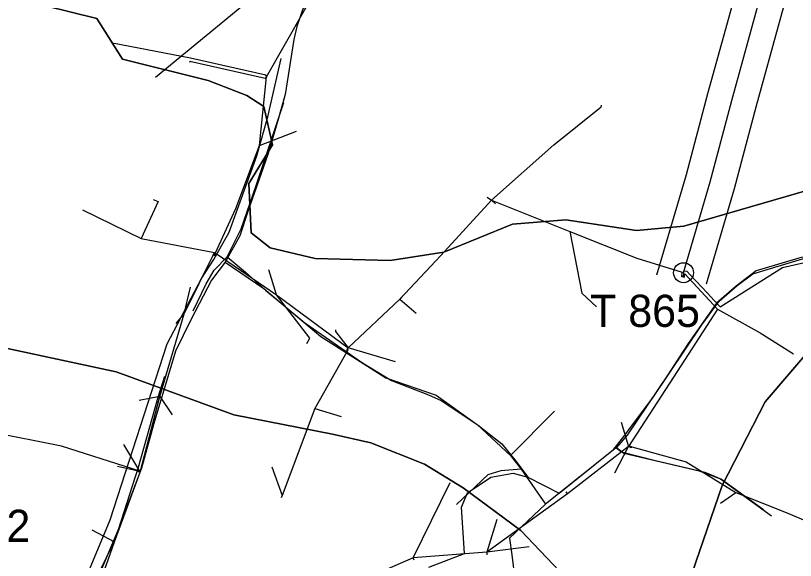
# Model space of a CAD drawing. Extents: x -694504 to -690518, y -983661 to -978958.
# Drawn here: x -692421.3 to -692057.3, y -981693.8 to -981439.4 of the extents above; entities that cross this region are included whole.
import ezdxf

# ---------------------------------------------------------------- set-up
doc = ezdxf.new("R2010")
doc.units = 0
for name, color, linetype in [('BPEJ', 7, 'Continuous'), ('kabelové a venkovní rozvody telefonu', 7, 'Continuous'), ('kanalizace', 7, 'Continuous'), ('ochranné pásmo vedení', 7, 'Continuous'), ('trafostanice', 7, 'Continuous'), ('třídy přednosti v ochraně ZP', 7, 'Continuous'), ('vedení NN', 7, 'Continuous'), ('vedení VN 35kV', 7, 'Continuous'), ('vodovodní řad', 7, 'Continuous')]:
    doc.layers.add(name, color=color, linetype=linetype)

msp = doc.modelspace()

# ---------------------------------------------------------------- linework, layer by layer
at = {"layer": 'BPEJ'}
for points in [[(-692030.4, -981514.81), (-692109.4, -981537.81), (-692131.4, -981539.81), (-692164.4, -981534.81), (-692189.4, -981536.81), (-692221.4, -981549.81), (-692246.4, -981553.81), (-692281.4, -981552.81), (-692302.4, -981547.81), (-692311.4, -981540.81), (-692312.4, -981517.81), (-692301.4, -981499.81), (-692305.4, -981481.81), (-692313.4, -981476.81), (-692331.4, -981469.81), (-692371.4, -981459.81), (-692383.4, -981440.81), (-692419.4, -981431.81)], [(-692419.4, -981431.81), (-692383.4, -981440.81), (-692371.4, -981459.81), (-692331.4, -981469.81), (-692313.4, -981476.81), (-692305.4, -981481.81), (-692301.4, -981499.81), (-692312.4, -981517.81), (-692311.4, -981540.81), (-692302.4, -981547.81), (-692281.4, -981552.81), (-692246.4, -981553.81), (-692221.4, -981549.81), (-692189.4, -981536.81), (-692164.4, -981534.81), (-692131.4, -981539.81), (-692109.4, -981537.81), (-692030.4, -981514.81)], [(-692048.4, -981592.81), (-692071.4, -981619.81), (-692091.4, -981658.81), (-692121.4, -981745.81), (-692122.4, -981762.81), (-692129.4, -981747.81), (-692146.4, -981720.81), (-692185.4, -981679.81), (-692212.4, -981659.81), (-692230.4, -981648.81), (-692255.4, -981638.81), (-692273.4, -981634.81), (-692319.4, -981625.81), (-692374.4, -981605.81), (-692448.4, -981589.81)], [(-692448.4, -981589.81), (-692374.4, -981605.81), (-692319.4, -981625.81), (-692273.4, -981634.81), (-692255.4, -981638.81), (-692230.4, -981648.81), (-692212.4, -981659.81), (-692185.4, -981679.81), (-692146.4, -981720.81), (-692129.4, -981747.81), (-692122.4, -981762.81), (-692122.4, -981762.81), (-692131.4, -981839.81), (-692140.4, -981853.81), (-692186.4, -981898.81), (-692262.4, -982000.81), (-692301.4, -982096.81)], [(-692040.4, -981946.81), (-692057.4, -981978.81), (-692066.4, -982000.81), (-692073.4, -982026.81), (-692083.4, -981992.81), (-692073.4, -981913.81), (-692069.4, -981844.81), (-692080.4, -981831.81), (-692109.4, -981808.81), (-692131.4, -981839.81), (-692122.4, -981762.81), (-692121.4, -981745.81), (-692091.4, -981658.81), (-692071.4, -981619.81), (-692048.4, -981592.81)]]:
    msp.add_lwpolyline(points, dxfattribs=at)
at = {"layer": 'kabelové a venkovní rozvody telefonu'}
for points in [[(-692322.48, -981552.13), (-692316.04, -981538.95), (-692309.01, -981518.73), (-692296.14, -981479.93)], [(-692338.37, -981577.29), (-692332.4, -981564.62), (-692328.62, -981558.33), (-692322.48, -981552.13), (-692313.98, -981559.16), (-692304.61, -981567.66), (-692286.25, -981582.81), (-692259.31, -981601.57), (-692245.84, -981609.77), (-692228.57, -981616.51), (-692222.71, -981619.14), (-692205.43, -981630.57), (-692194.31, -981639.36), (-692187.57, -981647.56), (-692182.22, -981654.98)], [(-692141.29, -981640.86), (-692138.01, -981636.65), (-692123.86, -981617.8), (-692101.02, -981583.81), (-692092.86, -981572.73), (-692084.43, -981565.46), (-692077.19, -981559.95), (-692048.89, -981551.49)], [(-692351.73, -981607.84), (-692354.94, -981617.65), (-692364.02, -981650.47), (-692374.85, -981683.8), (-692381, -981696.69), (-692385.95, -981706.26), (-692390.35, -981717.4), (-692391.52, -981722.38), (-692391.52, -981725.6), (-692389.76, -981730.29), (-692384.78, -981735.27), (-692373.07, -981744.64), (-692354.95, -981754.1)], [(-692228.42, -981696.87), (-692211.68, -981690.59), (-692213.16, -981668.95), (-692210.33, -981662.17), (-692199.42, -981654.98), (-692189.09, -981652.97), (-692182.22, -981654.98), (-692167.63, -981662.43), (-692142.15, -981641.97), (-692141.29, -981640.86), (-692138.46, -981643.07), (-692122.65, -981647.17), (-692102.74, -981651.85), (-692092.19, -981655.66), (-692082.53, -981662.7), (-692068.47, -981672.95)]]:
    msp.add_lwpolyline(points, dxfattribs=at)
at = {"layer": 'kanalizace'}
msp.add_lwpolyline([(-692637.3, -982018.94), (-692543.86, -981996.43), (-692482.24, -981915), (-692389.85, -981795.54), (-692370.2, -981769.76), (-692361.24, -981760.23), (-692369.79, -981750.51), (-692394.74, -981731.55), (-692395.7, -981719.37), (-692377.18, -981674.9), (-692350.54, -981592.69), (-692334.59, -981562.19), (-692328.73, -981553.37), (-692321.59, -981540.53), (-692308.62, -981504.97), (-692303.5, -981486.69), (-692297.29, -981459.54)], dxfattribs=at)
at = {"layer": 'ochranné pásmo vedení'}
for points in [[(-692476.97, -981718.1), (-692516.45, -981680.3), (-692507.47, -981641.12), (-692491.56, -981571.66), (-692478.56, -981516.66), (-692467.55, -981468.63), (-692453.55, -981407.64), (-692440.55, -981351.64), (-692429.53, -981303.54), (-692425.91, -981286.65), (-692239.14, -981321.55), (-692136.15, -981340.55), (-692063.84, -981354.16), (-692072.29, -981383.76), (-692085.31, -981428.8), (-692098.34, -981475.94), (-692108.32, -981513.84), (-692122.09, -981560.59)], [(-692098.78, -981564.62), (-692085.68, -981520.16), (-692075.66, -981482.06), (-692062.69, -981435.2), (-692049.71, -981390.24), (-692040.57, -981358.27), (-691970.98, -981369.58), (-691892.99, -981383.58), (-691578.35, -981435.35), (-691505.97, -981436.12), (-691403.79, -981436.1), (-691320.85, -981435.75), (-691226.93, -981433.75), (-691115.11, -981434.75), (-691018, -981435.75), (-690919.94, -981434.75), (-690865, -981434.75), (-690798.01, -981434.75), (-690720.4, -981434.84), (-690660.99, -981434.75), (-690632.73, -981444.66)]]:
    msp.add_lwpolyline(points, dxfattribs=at)
at = {"layer": 'trafostanice'}
msp.add_ellipse((-692109.51, -981559.46), major_axis=(0, 4.66), ratio=0.997816, dxfattribs=at)
at = {"layer": 'vedení NN'}
for points in [[(-692304.18, -981468.07), (-692286.37, -981436.95), (-692269.09, -981406.97), (-692250.04, -981388), (-692230.09, -981367.77)], [(-692304.18, -981468.07), (-692286.37, -981436.95), (-692269.09, -981406.97), (-692250.04, -981388), (-692230.09, -981367.77)], [(-692304.18, -981468.07), (-692304.47, -981467.19), (-692339.62, -981459.26), (-692376.04, -981452.38)], [(-692304.18, -981468.07), (-692304.47, -981467.19), (-692339.62, -981459.26), (-692376.04, -981452.38)], [(-692304.18, -981468.07), (-692304.79, -981468.75), (-692339.98, -981460.82), (-692340.11, -981461.26)], [(-692304.18, -981468.07), (-692304.79, -981468.75), (-692339.98, -981460.82), (-692340.11, -981461.26)], [(-692307.49, -981500.06), (-692304.18, -981468.07)], [(-692307.49, -981500.06), (-692304.18, -981468.07)], [(-692199.19, -981525.67), (-692169.98, -981499.82), (-692148.01, -981482.08), (-692147.87, -981481.2)], [(-692307.49, -981500.06), (-692290.15, -981493.46)], [(-692307.49, -981500.06), (-692290.15, -981493.46)], [(-692328.06, -981550.23), (-692318.5, -981529.53), (-692307.49, -981500.06)], [(-692328.06, -981550.23), (-692318.5, -981529.53), (-692307.49, -981500.06)], [(-692201.2, -981524.18), (-692199.19, -981525.67)], [(-692357.03, -981525.35), (-692354.72, -981526.22), (-692362.73, -981543.46)], [(-692357.03, -981525.35), (-692354.72, -981526.22), (-692362.73, -981543.46)], [(-692241.88, -981571.78), (-692222.74, -981551.41), (-692199.19, -981525.67)], [(-692241.88, -981571.78), (-692222.74, -981551.41), (-692199.19, -981525.67)], [(-692199.19, -981525.67), (-692162.59, -981540.3)], [(-692199.19, -981525.67), (-692197.34, -981527.36)], [(-692390.11, -981530.07), (-692362.73, -981543.46)], [(-692390.11, -981530.07), (-692362.73, -981543.46)], [(-692162.59, -981540.3), (-692157.02, -981569.01), (-692150.09, -981575.45)], [(-692162.59, -981540.3), (-692131.29, -981552.63), (-692110.09, -981559.22)], [(-692362.73, -981543.46), (-692328.4, -981550.02)], [(-692362.73, -981543.46), (-692328.4, -981550.02)], [(-692092.46, -981575.4), (-692063.34, -981556.99), (-692020.86, -981547.32)], [(-692342.67, -981578.61), (-692328.4, -981550.02)], [(-692342.67, -981578.61), (-692328.4, -981550.02)], [(-692328.67, -981551.26), (-692329.03, -981551.09), (-692328.4, -981550.02)], [(-692328.67, -981551.26), (-692329.03, -981551.09), (-692328.4, -981550.02)], [(-692328.67, -981551.26), (-692328.06, -981550.23)], [(-692328.67, -981551.26), (-692328.06, -981550.23)], [(-692328.67, -981551.26), (-692328.3, -981551.43), (-692327.71, -981550.43)], [(-692328.67, -981551.26), (-692328.3, -981551.43), (-692327.71, -981550.43)], [(-692327.71, -981550.43), (-692299.46, -981569.76)], [(-692327.71, -981550.43), (-692299.46, -981569.76)], [(-692299.46, -981569.76), (-692303.13, -981558.09)], [(-692299.46, -981569.76), (-692303.13, -981558.09)], [(-692109.65, -981561.46), (-692110.25, -981561.41), (-692110.09, -981559.22)], [(-692109.65, -981561.46), (-692109.45, -981561.46), (-692109.31, -981559.55), (-692109.24, -981558.6), (-692107.98, -981558.71), (-692106.21, -981560.63), (-692098.37, -981569.04), (-692095.22, -981572.43), (-692092.46, -981575.4)], [(-692109.65, -981561.46), (-692109.05, -981561.5), (-692108.95, -981560.04), (-692093.7, -981576.44)], [(-692342.67, -981578.61), (-692339.67, -981566.27)], [(-692342.67, -981578.61), (-692339.67, -981566.27)], [(-692299.46, -981569.76), (-692265.99, -981594.6)], [(-692285.28, -981592.44), (-692283.96, -981589.97), (-692299.46, -981569.76)], [(-692299.46, -981569.76), (-692265.99, -981594.6)], [(-692285.28, -981592.44), (-692283.96, -981589.97), (-692299.46, -981569.76)], [(-692265.99, -981594.6), (-692241.88, -981571.78)], [(-692265.99, -981594.6), (-692241.88, -981571.78)], [(-692241.08, -981570.79), (-692241.88, -981571.78)], [(-692241.08, -981570.79), (-692241.88, -981571.78)], [(-692241.88, -981571.78), (-692234.39, -981578.41)], [(-692241.88, -981571.78), (-692234.39, -981578.41)], [(-692354.05, -981617.2), (-692342.67, -981578.61)], [(-692354.05, -981617.2), (-692342.67, -981578.61)], [(-692346.29, -981583.25), (-692342.67, -981578.61)], [(-692346.29, -981583.25), (-692342.67, -981578.61)], [(-692093.7, -981576.44), (-692114.24, -981608.18), (-692135.16, -981640.63)], [(-692093.7, -981576.44), (-692073.72, -981587.56), (-692058.16, -981597.26)], [(-692271.99, -981586.18), (-692271.99, -981586.97), (-692265.99, -981594.6)], [(-692271.99, -981586.18), (-692271.99, -981586.97), (-692265.99, -981594.6)], [(-692363.24, -981652.11), (-692399.84, -981640.37), (-692432.85, -981633.91), (-692467.53, -981622.8), (-692500.59, -981611.45), (-692535.39, -981599.72), (-692572.99, -981587.27)], [(-692363.24, -981652.11), (-692399.84, -981640.37), (-692432.85, -981633.91), (-692467.53, -981622.8), (-692500.59, -981611.45), (-692535.39, -981599.72), (-692572.99, -981587.27)], [(-692266.59, -981595.73), (-692266.42, -981595.84), (-692265.99, -981595.26), (-692281.69, -981622.84)], [(-692266.59, -981595.73), (-692266.42, -981595.84), (-692265.99, -981595.26), (-692281.69, -981622.84)], [(-692266.59, -981595.73), (-692266.75, -981595.61), (-692265.99, -981594.6)], [(-692266.59, -981595.73), (-692266.75, -981595.61), (-692265.99, -981594.6)], [(-692244, -981601), (-692265.99, -981594.6)], [(-692244, -981601), (-692265.99, -981594.6)], [(-692354.05, -981617.2), (-692363.55, -981619.11)], [(-692354.05, -981617.2), (-692363.55, -981619.11)], [(-692363.14, -981652.52), (-692354.05, -981617.2)], [(-692363.14, -981652.52), (-692354.05, -981617.2)], [(-692354.05, -981617.2), (-692348.28, -981625.76)], [(-692354.05, -981617.2), (-692348.28, -981625.76)], [(-692281.69, -981622.84), (-692296.9, -981663.39)], [(-692281.69, -981622.84), (-692296.9, -981663.39)], [(-692281.69, -981622.84), (-692269.37, -981626.66)], [(-692281.69, -981622.84), (-692269.37, -981626.66)], [(-692138.57, -981629.29), (-692135.16, -981640.63)], [(-692363.24, -981652.11), (-692370.79, -981639.61)], [(-692363.24, -981652.11), (-692370.79, -981639.61)], [(-692135.16, -981640.63), (-692163.66, -981662.66)], [(-692141.57, -981652.95), (-692135.16, -981640.63)], [(-692133.93, -981641), (-692134.01, -981641.19), (-692135.16, -981640.63)], [(-692134.69, -981640.41), (-692108.2, -981647.79), (-692085.04, -981662.04)], [(-692133.93, -981641), (-692133.85, -981640.82), (-692134.69, -981640.41)], [(-692373.77, -981649.74), (-692363.24, -981652.11)], [(-692373.77, -981649.74), (-692363.24, -981652.11)], [(-692301.65, -981650.02), (-692296.9, -981663.39)], [(-692301.65, -981650.02), (-692296.9, -981663.39)], [(-692375.21, -981685.03), (-692363.14, -981652.52)], [(-692375.21, -981685.03), (-692363.14, -981652.52)], [(-692363.14, -981652.52), (-692364.16, -981652.38), (-692364.14, -981652.18)], [(-692363.14, -981652.52), (-692364.16, -981652.38), (-692364.14, -981652.18)], [(-692364.14, -981652.18), (-692364.13, -981651.99), (-692363.24, -981652.11)], [(-692364.14, -981652.18), (-692364.13, -981651.99), (-692363.24, -981652.11)], [(-692235.68, -981692.51), (-692218.43, -981657.42)], [(-692235.68, -981692.51), (-692218.43, -981657.42)], [(-692163.66, -981662.66), (-692201.35, -981689.88)], [(-692164.46, -981661.68), (-692163.66, -981662.66)], [(-692092.18, -981667.12), (-692085.04, -981662.04)], [(-692085.04, -981662.04), (-692060.84, -981671.79)], [(-692296.9, -981663.39), (-692297.3, -981664.6)], [(-692296.9, -981663.39), (-692297.3, -981664.6)], [(-692060.84, -981671.79), (-692032.41, -981683.91), (-692001.06, -981694.15), (-691966.1, -981706.21), (-691937.97, -981715.65), (-691916.06, -981721.56), (-691918.14, -981720.74)], [(-692196.67, -981674.69), (-692201.35, -981689.88)], [(-692385.68, -981679.52), (-692375.21, -981685.03)], [(-692385.68, -981679.52), (-692375.21, -981685.03)], [(-692376.41, -981684.64), (-692375.21, -981685.03)], [(-692376.41, -981684.64), (-692375.21, -981685.03)], [(-692389.74, -981726.41), (-692375.21, -981685.03)], [(-692389.74, -981726.41), (-692375.21, -981685.03)], [(-692181.51, -981687.44), (-692201.35, -981689.88)], [(-692201.35, -981689.88), (-692235.68, -981692.51)], [(-692201.35, -981689.88), (-692235.68, -981692.51)], [(-692201.35, -981689.88), (-692201.3, -981691.14)], [(-692235.68, -981692.51), (-692266.02, -981705.85)], [(-692235.68, -981692.51), (-692266.02, -981705.85)], [(-692235.3, -981693.72), (-692235.68, -981692.51)], [(-692235.3, -981693.72), (-692235.68, -981692.51)]]:
    msp.add_lwpolyline(points, dxfattribs=at)
at = {"layer": 'vedení VN 35kV'}
msp.add_lwpolyline([(-692109.51, -981559.46), (-692097, -981517), (-692087, -981479), (-692074, -981432), (-692061, -981387), (-692049, -981345), (-692029, -981294), (-692008, -981241), (-691986, -981188), (-691990, -981131), (-691993, -981064), (-691997, -980994), (-691952, -980955), (-691906, -980915), (-691864.8, -980876.87), (-691830.33, -980911.56), (-691803.29, -980937.37)], dxfattribs=at)
at = {"layer": 'vodovodní řad'}
for points in [[(-691952.28, -981239.87), (-691994.16, -981283.53), (-692016.03, -981284.05), (-692075.58, -981304.29), (-692142.96, -981360.36), (-692143.71, -981380.97), (-692213.37, -981379.85), (-692228.6, -981388.76), (-692264.18, -981392.95), (-692318.32, -981437.42), (-692356, -981468.38)], [(-692284.73, -981428.92), (-692289.95, -981444.58), (-692291.44, -981450.54), (-692295.54, -981476.22), (-692298.9, -981488.34), (-692303.54, -981504.27), (-692312.83, -981530.88), (-692316.57, -981542.29), (-692323.49, -981554.53), (-692329.81, -981562.87), (-692339.45, -981581.45), (-692346.6, -981596.1), (-692356.78, -981629.87), (-692362.51, -981650.64), (-692373.6, -981679.74), (-692384.92, -981706.74), (-692389.75, -981718.96), (-692388.26, -981731.64), (-692361.43, -981749.91), (-692367.98, -981754.94), (-692376.35, -981765.9), (-692385.69, -981778.47), (-692399.12, -981797.49), (-692433.91, -981841.96)], [(-691925.74, -981524.9), (-691945.82, -981526.14), (-691955.93, -981527.64), (-692017.33, -981543.71), (-692055.72, -981552.66), (-692075.66, -981558.63), (-692084.97, -981565.71), (-692094.1, -981573.73), (-692107.3, -981592.51), (-692116.79, -981607.21), (-692135.79, -981635.34), (-692140.82, -981641.12), (-692173.93, -981667.53)], [(-692323.49, -981554.53), (-692305.35, -981566.81), (-692278.76, -981589.3), (-692248.45, -981608.57), (-692224.97, -981616.58), (-692205.78, -981630.38), (-692190.31, -981644.85), (-692185.35, -981651.12), (-692173.93, -981667.53), (-692190.72, -981683.35), (-692189.65, -981691.22), (-692188.21, -981702.68), (-692188.21, -981712.35), (-692191.79, -981745.29), (-692186.07, -981765.34), (-692188.21, -981773.93), (-692189.92, -981781.63), (-692191.23, -981789.38), (-692191.16, -981792.44), (-692187.85, -981820.64), (-692188.56, -981831.03), (-692191.78, -981841.41), (-692203.95, -981858.95), (-692210.39, -981866.11)], [(-692169.77, -981624.15), (-692190.31, -981644.85)], [(-692140.82, -981641.12), (-692137.32, -981643.63), (-692099.49, -981652.63), (-692091.81, -981655.81), (-692072.15, -981670.05)], [(-692185.35, -981651.12), (-692194.86, -981651.88), (-692200.85, -981653.75), (-692215.46, -981667.61)]]:
    msp.add_lwpolyline(points, dxfattribs=at)

# ---------------------------------------------------------------- texts
at = {"layer": 'trafostanice'}
msp.add_text('T 865', height=15, dxfattribs=at).set_placement((-692153.13, -981584.76))
at = {"layer": 'třídy přednosti v ochraně ZP'}
msp.add_text('7.15.12', height=15, dxfattribs=at).set_placement((-692481.36, -981685.11))

doc.saveas('drawing.dxf')
